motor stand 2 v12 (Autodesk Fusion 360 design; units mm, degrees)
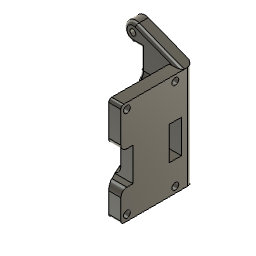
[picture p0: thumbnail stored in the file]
sketch "草图1" plane through (0, 0, 0) normal (1, 0, 0) x axis (0, 1, 0)
  line L1 (-10, -17) -> (10, -17)
  line L2 (10, -7.25) -> (10, 3.75)
  line L3 (10, 3.75) -> (6, 3.75)
  line L4 (-10, 3.75) -> (-6, -7.25)
  line L5 (-10, -7.25) -> (-10, 3.75)
  line L6 (-10, 17) -> (10, -17)
  line L7 (6, 3.75) -> (6, -7.25)
  line L8 (6, -7.25) -> (10, -7.25)
  line L9 (10, 0) -> (-10, 0)
  line L10 (10, -17) -> (10, 17)
  line L11 (-6, -7.25) -> (-10, -7.25)
  line L12 (-10, 17) -> (-10, -17)
  line L13 (10, 17) -> (-10, 17)
  line L14 (-6, 3.75) -> (-10, -7.25)
  line L15 (0, -17) -> (0, 17)
  line L16 (-10, 3.75) -> (-6, 3.75)
  line L17 (-6, 3.75) -> (-6, -7.25)
  line L18 (10, 17) -> (-10, -17)
  line L19 (10, -1.75) -> (-10, -1.75)
  circle C1 centre (-8, 15) radius 1.125
  circle C2 centre (-8, -15) radius 1.125
  circle C3 centre (8, 15) radius 1.125
  circle C4 centre (0, 8) radius 1.3
  circle C5 centre (0, 8) radius 4
  circle C6 centre (0, 8) radius 3
  circle C7 centre (8, -15) radius 1.125
  point P5 (0, 0)
  point P15 (0, 0)
  point P6 (-8, -1.75)
  point P8 (-10, -7.25)
  point P25 (0, 17)
  point P26 (0, -17)
  point P18 (10, -7.25)
  point P11 (6, -7.25)
  point P13 (-6, -7.25)
  point P9 (6, 3.75)
  point P24 (-6, 3.75)
  point P7 (-10, 3.75)
  point P14 (10, 3.75)
  point P4 (10, -1.75)
  point P20 (-10, -1.75)
  point P10 (0, 8)
  point P21 (-10, 0)
  point P29 (10, 0)
  point P16 (10, 17)
  point P17 (-10, 17)
  point P22 (10, -17)
  point P28 (-8, 15)
  horizontal L1
  perpendicular L1 L12
  parallel L1 L13
  parallel L10 L12
  coincident P5 L6
  coincident P5 L18
  coincident P5 P15
  horizontal L11
  perpendicular L11 L17
  parallel L11 L16
  parallel L5 L17
  coincident P6 L14
  coincident P6 L4
  coincident P8 L12
  coincident P6 L19
  midpoint P25 L13
  midpoint P26 L1
  symmetric P8 P18 L15
  symmetric P11 P13 L15
  symmetric P9 P24 L15
  symmetric P7 P14 L15
  midpoint P4 L2
  midpoint P20 L5
  coincident P10 L15
  midpoint P21 L12
  midpoint P29 L10
  symmetric C1 C3 L15
  symmetric C1 C2 L9
  symmetric C3 L9 C7
  concentric C4 C6
  concentric C5 C6
  dimension "d1" distance P16 P17 = 20
  dimension "d2" distance P16 P22 = 34
  dimension "d3" distance P13 P24 = 11
  dimension "d4" distance P7 P24 = 4
  dimension "d5" diameter C4 = 2.6
  dimension "d6" distance P28 L15 = 8
  dimension "d7" distance P28 L9 = 15
  dimension "d8" diameter C1 = 2.25
  dimension "d9" distance P10 P28 = 7
  dimension "d10" diameter C6 = 6
  dimension "d11" diameter C5 = 8
  dimension "d12" distance L1 L8 = 9.75 (= "10.25 mm - 0.5 mm")
extrude "拉伸1" new body sketch "草图1" profile of L1 C1 C2 L3 C3 L7 L8 L10 L11 L12 C7 L13 L16 L17 along normal blind 4
sketch "草图2" plane through (0, 10, 0) normal (0, 1, 0) x axis (-1, 0, 0)
  line L1 (0, 17) -> (0, 3.75)
  line L2 (-4, 17) -> (0, 17)
  line L3 (-4, 3.75) -> (-4, 17)
  line L4 (0, 3.75) -> (-4, 3.75)
  line L5 (0, 17) -> (-4, 17)
  line L6 (0, -17) -> (0, 17)
  line L7 (-4, -17) -> (0, -17)
  line L8 (-4, 17) -> (-4, -17)
  line L9 (-13.5, 17) -> (-4, 17)
  line L10 (-13.5, -17) -> (-13.5, 17)
  line L11 (-4, -17) -> (-13.5, -17)
  line L12 (-4, 17) -> (-4, -17)
  line L13 (0, 0) -> (-13.5, 0)
  line L14 (-14.9132, 22.7962) -> (0, 17)
  line L15 (-14.9132, -22.7962) -> (0, -17)
  line L16 (-16, 17) -> (-13.5, 17)
  line L17 (-16, -17) -> (-13.5, -17)
  line L18 (-2, -17) -> (-2, 17)
  line L19 (10.9132, 22.7962) -> (-4, 17)
  line L20 (9.5, 17) -> (0, 17)
  line L21 (9.5, -17) -> (9.5, 17)
  line L22 (12, 17) -> (9.5, 17)
  line L23 (0, -17) -> (9.5, -17)
  line L24 (12, -17) -> (9.5, -17)
  line L25 (10.9132, -22.7962) -> (-4, -17)
  circle C1 centre (-6, 0) radius 0.975
  circle C2 centre (-16, 20) radius 0.975
  circle C3 centre (-16, -20) radius 0.975
  circle C4 centre (-16, 20) radius 3
  circle C5 centre (-16, -20) radius 3
  circle C6 centre (12, 20) radius 3
  circle C7 centre (12, 20) radius 0.975
  circle C8 centre (12, -20) radius 3
  circle C9 centre (12, -20) radius 0.975
  circle C10 centre (2, 0) radius 0.975
  point P4 (-4, 17)
  point P6 (-4, 17)
  point P13 (-13.5, 0)
  point P1 (0, 0)
  point P14 (0, 0)
  point P3 (0, 17)
  point P19 (0, 17)
  point P20 (-14.9132, 22.7962)
  point P21 (0, -17)
  point P22 (-14.9132, -22.7962)
  point P24 (-16, 17)
  point P25 (-16, -17)
  point P26 (-2, 17)
  point P27 (-2, -17)
  point P30 (0, 17)
  point P10 (-13.5, 17)
  point P31 (9.5, 17)
  point P11 (-13.5, -17)
  point P34 (9.5, -17)
  point P12 (-4, -17)
  point P36 (0, -17)
  point P28 (-4, 17)
  point P29 (10.9132, 22.7962)
  point P40 (-4, -17)
  point P41 (10.9132, -22.7962)
  point P35 (12, 17)
  point P37 (12, -17)
  point P7 (0, 17)
  point P8 (0, -17)
  point P16 (-16, 20)
  point P17 (-16, -20)
  point P15 (-6, 0)
  horizontal L5
  vertical L6
  horizontal L7
  vertical L8
  coincident P4 P6
  horizontal L9
  vertical L10
  horizontal L11
  vertical L12
  collinear L7 L11
  midpoint L10 P13
  coincident P1 P14
  equal C1 C2
  symmetric L13 C2 C3
  concentric C2 C4
  tangent L9 C4
  coincident P3 P19
  coincident C4 P20
  tangent C4 L14
  symmetric L13 C4 C5
  symmetric L13 P19 P21
  symmetric L13 P20 P22
  coincident C4 P24
  tangent C4 L16
  perpendicular L10 L16
  coincident C5 P25
  tangent C5 L17
  midpoint L5 P26
  midpoint L7 P27
  symmetric P6 L18 P30
  symmetric P10 L18 P31
  symmetric P11 L18 P34
  symmetric P12 L18 P36
  symmetric C2 L18 C7
  symmetric C3 L18 C9
  symmetric C4 L18 C6
  symmetric P19 L18 P28
  symmetric P20 L18 P29
  symmetric P21 L18 P40
  symmetric P22 L18 P41
  symmetric C5 L18 C8
  symmetric P24 L18 P35
  symmetric P25 L18 P37
  symmetric C1 L18 C10
  dimension "d15" distance P7 P8 = 34
  dimension "d16" distance P6 P7 = 4
  dimension "d17" diameter C1 = 1.95
  dimension "d18" distance P16 P17 = 40
  dimension "d19" distance P15 P16 = 10
  dimension "d20" distance L12 P15 = 2
  dimension "d21" distance L10 P16 = 2.5
extrude "拉伸2" add sketch "草图2" profile of L1 L2 L3 L4 L5 L6 L7 L8 L12 L14 L15 L19 L20 C6 C7 L21 L22 L23 L24 C8 C9 L25 C10 along normal blind 4
sketch "草图3" plane through (0, 0, 17) normal (0, 0, 1) x axis (-1, 0, 0)
  line L1 (0, 10) -> (0, -10)
  line L2 (-4, 10) -> (0, 10)
  line L3 (-4, -10) -> (-4, 10)
  line L4 (0, -10) -> (-4, -10)
  line L5 (9.5, -10) -> (0, 10)
  line L6 (0, -10) -> (9.5, -10)
  point P3 (0, 10)
  point P7 (0, 10)
  point P6 (9.5, -10)
  point P8 (9.5, -10)
  point P2 (0, -10)
  point P9 (0, -10)
  coincident P3 P7
  coincident P6 P8
  coincident P2 P9
extrude "拉伸3" sketch "草图3" profile of L1 L5 L6 blind 4
extrude "拉伸4" sketch "草图3" profile of L1 L5 L6 blind -4
fillet "圆角1" radius 3
fillet "圆角2" radius 1
fillet "圆角3" radius 2
fillet "圆角4" radius 1
fillet "圆角5" radius 1
fillet "圆角6" radius 2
